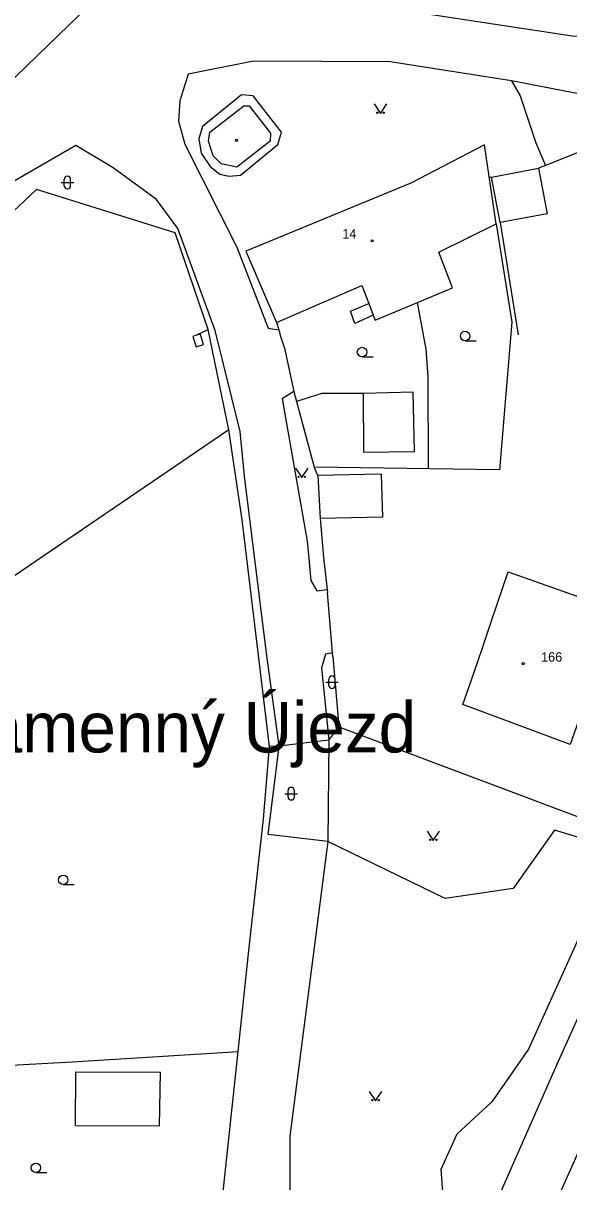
# Model space of a CAD drawing. Extents: x -836739 to -834468, y -1071001 to -1070126.
# Drawn here: x -836674.9 to -836631.7, y -1070409.4 to -1070317.5 of the extents above; entities that cross this region are included whole.
import ezdxf

# ---------------------------------------------------------------- set-up
doc = ezdxf.new("R2010")
doc.units = 0
for name, color, linetype in [('f001_pol_linie', 7, 'Continuous'), ('f001_pol_texty', 7, 'Continuous'), ('f001_pol_znacky', 7, 'Continuous')]:
    doc.layers.add(name, color=color, linetype=linetype)

msp = doc.modelspace()

# ---------------------------------------------------------------- linework, layer by layer
at = {"layer": 'f001_pol_linie'}
for points in [[(-836630.51, -1070318.53), (-836631.23, -1070318.61), (-836645.35, -1070316.45), (-836656.37, -1070316.2), (-836658.11, -1070315.12), (-836659.3, -1070313.99), (-836659.93, -1070312.1), (-836657.97, -1070309.39), (-836649.57, -1070300.23), (-836643.77, -1070294.82), (-836640.08, -1070293.18), (-836638.52, -1070292.93), (-836636.78, -1070292.94), (-836635.2, -1070293.36), (-836633.37, -1070294.59), (-836629.87, -1070302.53), (-836628.06, -1070308.61), (-836626.86, -1070313.5), (-836627.32, -1070316.48), (-836628.85, -1070317.93), (-836630.51, -1070318.53)], [(-836703.09, -1070353.49), (-836701.06, -1070351.9), (-836696.37, -1070345.09), (-836691.07, -1070338.71), (-836685.16, -1070331.14), (-836682.48, -1070327.94), (-836676.32, -1070322.57), (-836669.65, -1070316.08), (-836666.36, -1070313.03), (-836662.49, -1070307.65), (-836660.63, -1070303.86), (-836659.99, -1070300.78), (-836660.08, -1070298.96), (-836660.27, -1070297.93), (-836660.82, -1070296.56)], [(-836624.31, -1070324.48), (-836628.98, -1070323.51), (-836636.22, -1070322.11), (-836645.83, -1070320.62), (-836656.66, -1070320.57), (-836661.85, -1070321.59), (-836662.52, -1070323.7), (-836662.62, -1070325.33), (-836662.12, -1070327.15), (-836657.99, -1070335.31), (-836655.52, -1070341.75), (-836654.67, -1070341.86)], [(-836636.22, -1070322.11), (-836635.55, -1070323.3), (-836634.31, -1070327.05), (-836633.53, -1070328.84)], [(-836658.61, -1070329.67), (-836657.7, -1070329.6), (-836654.73, -1070327.17), (-836654.45, -1070326.18), (-836656.7, -1070323.32), (-836657.63, -1070323.23), (-836660.71, -1070325.75), (-836661.01, -1070326.72), (-836660.81, -1070327.85), (-836660.11, -1070328.92), (-836659.34, -1070329.52), (-836658.61, -1070329.67)], [(-836660.14, -1070326.18), (-836657.44, -1070324.1), (-836657.02, -1070324.09), (-836655.33, -1070326.28), (-836655.35, -1070326.91), (-836658, -1070328.96), (-836659.22, -1070328.71), (-836659.86, -1070328.06), (-836660.23, -1070326.91), (-836660.14, -1070326.18)], [(-836637.13, -1070410.36), (-836632.54, -1070399.93), (-836624.1, -1070381.23), (-836615.6, -1070365.58), (-836607.14, -1070355.56), (-836596.81, -1070346.2), (-836590.03, -1070339.5), (-836589.31, -1070338.79), (-836589.07, -1070337.69), (-836589.06, -1070336.43), (-836589.28, -1070334.96), (-836590.73, -1070333.14), (-836591.73, -1070332.35), (-836593.66, -1070331.61), (-836605.86, -1070329.36), (-836624.31, -1070324.48)], [(-836650.41, -1070367.5), (-836650.96, -1070367.6), (-836651.27, -1070368.67), (-836650.69, -1070374.42), (-836654.63, -1070374.88), (-836655.63, -1070367.52), (-836657.37, -1070353.48), (-836657.73, -1070349.93), (-836659.71, -1070341.92), (-836662.66, -1070333.84), (-836664.35, -1070331.52), (-836667.79, -1070329.01), (-836670.76, -1070327.26), (-836677.72, -1070331.28), (-836681.67, -1070335.86), (-836683.38, -1070337.84)], [(-836641.98, -1070335.71), (-836637.43, -1070333.46), (-836638.37, -1070327.19), (-836644.19, -1070330.24), (-836657.27, -1070335.64), (-836654.84, -1070341.3), (-836648.08, -1070338.36), (-836647.54, -1070339.78), (-836647.18, -1070340.71), (-836647.03, -1070341.09), (-836643.67, -1070339.7), (-836640.89, -1070338.54), (-836641.98, -1070335.71)], [(-836629.37, -1070327.18), (-836633.53, -1070328.84), (-836634.08, -1070329.05)], [(-836634.08, -1070329.05), (-836633.41, -1070332.67), (-836637.13, -1070333.36), (-836637.8, -1070329.75), (-836634.08, -1070329.05)], [(-836637.8, -1070329.75), (-836637.98, -1070329.79)], [(-836661.2, -1070342.3), (-836660.26, -1070341.85), (-836662.88, -1070334.18), (-836673.87, -1070330.74), (-836681.27, -1070337.68)], [(-836637.43, -1070333.46), (-836636.21, -1070341.27), (-836637.18, -1070352.98)], [(-836637.13, -1070333.36), (-836635.7, -1070342.27)], [(-836648.63, -1070341.36), (-836648.99, -1070340.38), (-836647.54, -1070339.78)], [(-836642.79, -1070352.9), (-836642.84, -1070345.59), (-836642.98, -1070343.39), (-836643.67, -1070339.7)], [(-836654.84, -1070341.3), (-836654.67, -1070341.86), (-836654.5, -1070342.48)], [(-836647.18, -1070340.71), (-836648.63, -1070341.36)], [(-836660.86, -1070342.23), (-836661.2, -1070342.3), (-836661.47, -1070342.4), (-836661.22, -1070343.21), (-836660.62, -1070343.02), (-836660.86, -1070342.23)], [(-836658.62, -1070349.8), (-836660.26, -1070341.85)], [(-836654.5, -1070342.48), (-836654.21, -1070343.33)], [(-836654.21, -1070343.33), (-836653.47, -1070346.76)], [(-836653.47, -1070346.76), (-836654.39, -1070347.34), (-836652.43, -1070358.62), (-836652.29, -1070360.01), (-836652.13, -1070361.76), (-836651.65, -1070362.56), (-836650.83, -1070362.47)], [(-836653.47, -1070346.76), (-836653.26, -1070347.55), (-836651.86, -1070352.77)], [(-836647.97, -1070346.92), (-836651.26, -1070346.93), (-836653.26, -1070347.55)], [(-836647.96, -1070351.58), (-836643.91, -1070351.53), (-836644.03, -1070346.82), (-836647.97, -1070346.92), (-836647.96, -1070351.58)], [(-836658.62, -1070349.8), (-836678.12, -1070363.07)], [(-836655.41, -1070374.93), (-836657.58, -1070356.93), (-836658.62, -1070349.8)], [(-836637.18, -1070352.98), (-836651.86, -1070352.77)], [(-836651.57, -1070353.42), (-836651.86, -1070352.77)], [(-836646.43, -1070356.74), (-836646.52, -1070353.31), (-836651.57, -1070353.42), (-836651.38, -1070356.83)], [(-836646.43, -1070356.74), (-836651.38, -1070356.83)], [(-836651.38, -1070356.83), (-836651.13, -1070359.92), (-836650.83, -1070362.47), (-836650.8, -1070362.7)], [(-836631.58, -1070374.75), (-836640.07, -1070371.58), (-836639.43, -1070369.7), (-836638.59, -1070367.26), (-836637.83, -1070365.02), (-836636.48, -1070361.06), (-836627.82, -1070364.13), (-836631.58, -1070374.75)], [(-836650.39, -1070367.79), (-836650.41, -1070367.5), (-836650.8, -1070362.7)], [(-836650.39, -1070367.79), (-836649.92, -1070373.36)], [(-836650.69, -1070374.42), (-836649.92, -1070373.36)], [(-836649.92, -1070373.36), (-836641.2, -1070376.64), (-836629.46, -1070381.04)], [(-836650.69, -1070374.42), (-836650.79, -1070382.45), (-836655.5, -1070381.91), (-836654.63, -1070374.88)], [(-836655.87, -1070380.69), (-836655.41, -1070374.93)], [(-836654.63, -1070374.88), (-836655.41, -1070374.93)], [(-836629.46, -1070381.04), (-836630.1, -1070382.38), (-836632.83, -1070381.55), (-836636.09, -1070386.19), (-836641.48, -1070386.97), (-836650.79, -1070382.45), (-836653.8, -1070405.82), (-836653.8, -1070413.64), (-836660.69, -1070431.93), (-836661.86, -1070443.82), (-836659.27, -1070448.73), (-836656.69, -1070455.24), (-836654.9, -1070458.11)], [(-836659.17, -1070411.22), (-836657.89, -1070399.1), (-836657.04, -1070391.1), (-836655.87, -1070380.69)], [(-836626.49, -1070382.25), (-836628.93, -1070385.76), (-836634.87, -1070398.93), (-836637.79, -1070403.09), (-836640.55, -1070405.67), (-836641.83, -1070408.47), (-836641.31, -1070415.5), (-836651.36, -1070445.15), (-836654.9, -1070458.11), (-836657.15, -1070469.1)], [(-836636.57, -1070420.39), (-836634.38, -1070415.61), (-836632.33, -1070410.21), (-836631.12, -1070407.53), (-836630.16, -1070405.38), (-836624, -1070391.72)], [(-836688.21, -1070400.8), (-836681.18, -1070400.48), (-836671.03, -1070399.94), (-836657.89, -1070399.1)], [(-836670.77, -1070404.97), (-836670.76, -1070400.72)], [(-836670.77, -1070404.97), (-836664.11, -1070405), (-836664.04, -1070400.76)], [(-836670.76, -1070400.72), (-836664.04, -1070400.76)]]:
    msp.add_lwpolyline(points, dxfattribs=at)
at = {"layer": 'f001_pol_znacky'}
for p, q in [((-836671.91, -1070330.19), (-836670.91, -1070330.19)), ((-836671.66, -1070330.44), (-836671.66, -1070329.94)), ((-836671.16, -1070330.44), (-836671.16, -1070329.94)), ((-836639.9, -1070342.735), (-836639.025, -1070342.735)), ((-836648.07, -1070344.005), (-836647.195, -1070344.005)), ((-836650.95, -1070369.82), (-836649.95, -1070369.82)), ((-836650.7, -1070370.07), (-836650.7, -1070369.57)), ((-836650.2, -1070370.07), (-836650.2, -1070369.57)), ((-836654.18, -1070378.66), (-836653.18, -1070378.66)), ((-836653.93, -1070378.91), (-836653.93, -1070378.41)), ((-836653.43, -1070378.91), (-836653.43, -1070378.41)), ((-836671.75, -1070385.875), (-836670.875, -1070385.875)), ((-836673.91, -1070408.705), (-836673.035, -1070408.705))]:
    msp.add_line(p, q, dxfattribs=at)
for points in [[(-836647.11, -1070323.95), (-836646.61, -1070324.7), (-836646.11, -1070323.95)], [(-836653.35, -1070352.83), (-836652.85, -1070353.58), (-836652.35, -1070352.83)], [(-836642.92, -1070381.63), (-836642.42, -1070382.38), (-836641.92, -1070381.63)], [(-836647.5, -1070402.27), (-836647, -1070403.02), (-836646.5, -1070402.27)]]:
    msp.add_lwpolyline(points, dxfattribs=at)
for centre, radius in [((-836646.86, -1070324.65), 0.05), ((-836646.36, -1070324.65), 0.05), ((-836658.02, -1070326.84), 0.0875), ((-836647.27, -1070334.81), 0.0875), ((-836639.9, -1070342.36), 0.375), ((-836648.07, -1070343.63), 0.375), ((-836653.1, -1070353.53), 0.05), ((-836652.6, -1070353.53), 0.05), ((-836635.3, -1070368.35), 0.0875), ((-836642.67, -1070382.33), 0.05), ((-836642.17, -1070382.33), 0.05), ((-836671.75, -1070385.5), 0.375), ((-836647.25, -1070402.97), 0.05), ((-836646.75, -1070402.97), 0.05), ((-836673.91, -1070408.33), 0.375)]:
    msp.add_circle(centre, radius, dxfattribs=at)
for centre, start, end in [((-836671.41, -1070329.94), 0, 179.99999), ((-836671.41, -1070330.44), 179.99999, 359.99999), ((-836650.45, -1070369.57), 0, 179.99999), ((-836650.45, -1070370.07), 179.99999, 359.99999), ((-836653.68, -1070378.41), 0, 179.99999), ((-836653.68, -1070378.91), 179.99999, 359.99999)]:
    msp.add_arc(centre, 0.25, start, end, dxfattribs=at)

# ---------------------------------------------------------------- texts
at = {"layer": 'f001_pol_texty'}
for s, height, p in [('14', 0.75, (-836649.63, -1070334.63)), ('166', 0.75, (-836633.88, -1070368.19)), ('Kamenný Újezd', 4, (-836681.54, -1070375.39))]:
    msp.add_text(s, height=height, dxfattribs=at).set_placement(p)

doc.saveas('drawing.dxf')
